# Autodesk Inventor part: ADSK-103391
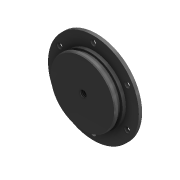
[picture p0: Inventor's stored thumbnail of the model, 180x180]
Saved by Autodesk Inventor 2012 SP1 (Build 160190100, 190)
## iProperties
Shininess: 0.0
Created: 2000-12
Part Number: ADSK-103391
Document SubType Name: Modeling
Stock Number: ADSK-103391
Density: 1 g/cm^3
Material: Default
Density: 0.0
Volumn: 0.0
Area: 0.0
PropertySet Name: Model Information
Control State: 0
Master: False
Checked Out: False
Author: gao
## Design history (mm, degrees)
node "Extrusion1" dims "d1" = 3.175, "d2" = 0
  sketch "Sketch1"
    geometry: C1 r 44.45 at (0, 0)
    constraints: 1 centre point
    dimensions: "d0" = 88.9 diameter of C1
node "Extrusion2" dims "d4" = 3.175, "d5" = 0
  sketch "Sketch2"
    geometry: C1 r 44.45 at (0, 0) reference; C2 r 31.75 at (0, 0)
    constraints: 1 centre point, 1 coincident
    dimensions: "d3" = 63.5 diameter of C2
node "Extrusion3" dims "d6" = 3.556, "d7" = 0
  sketch "Sketch3"
    geometry: C1 r 29.794 at (-0.822, 0)
    constraints: 1 centre point
    dimensions: "d11" = 59.5884 diameter of C1
node "Extrusion4" dims "d9" = 3.175, "d10" = 0
  sketch "Sketch4"
    geometry: C1 r 29.794 at (0, 0) reference; C2 r 31.75 at (0, 0)
    constraints: 1 centre point, 1 coincident
    dimensions: "d8" = 63.5 diameter of C2
node "Chamfer1" dims "d12" = 0.762, "d13" = 0.762, "d31" = 45 deg
node "Hole1" dims "d15" = 5.334, "d16" = 9.525, "d17" = 6.35, "d18" = 60 deg, "d19" = 19.05, "d20" = 118 deg
  sketch "Sketch5" dims "d14" = 76.2
    geometry: C1 r 44.45 at (0, 0) reference; 2 further points
    constraints: 1 coincident, 1 vertical alignment, 2 other
node "Circular Pattern1" dims "d21" = 60, "d23" = 60 deg
node "Hole2" dims "d24" = 6.4008, "d25" = 9.525, "d26" = 6.35, "d27" = 60 deg, "d28" = 19.05, "d29" = 118 deg, "d30" = 12.7
  sketch "Sketch6"
    geometry: C1 r 44.45 at (0, 0) reference; 1 further point
    constraints: 1 coincident
body "Solid1"
